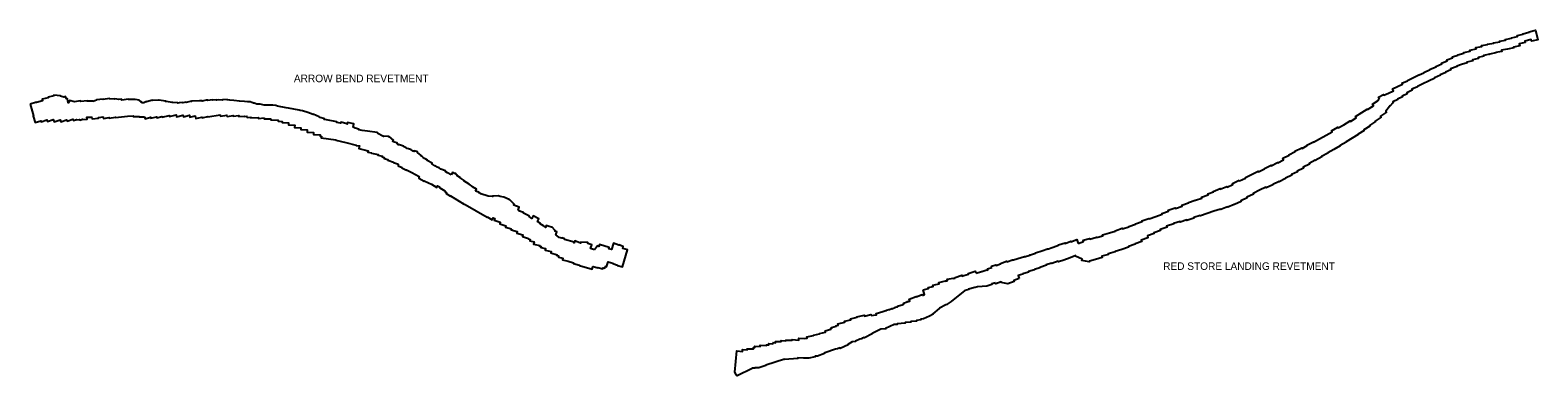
# Model space of a CAD drawing. Extents: x 2650582 to 3923188, y 277893 to 989177.
# Drawn here: x 3228750 to 3260686, y 811900 to 819222 of the extents above; entities that cross this region are included whole.
import ezdxf

# ---------------------------------------------------------------- set-up
doc = ezdxf.new("R2010")
doc.units = 0
doc.layers.add('Level 3', color=7, linetype='Continuous')

msp = doc.modelspace()

# ---------------------------------------------------------------- linework, layer by layer
at = {"layer": 'Level 3'}
for points in [[(3258408, 818391), (3258408, 818393), (3258531, 818448), (3258528, 818455), (3258651, 818509), (3258645, 818526), (3258768, 818574), (3258760, 818595), (3258880, 818639), (3258875, 818654), (3258990, 818691), (3258988, 818697), (3259120, 818737), (3259118, 818746), (3259253, 818779), (3259248, 818801), (3259377, 818827), (3259371, 818852), (3259498, 818879), (3259494, 818896), (3259621, 818920), (3259620, 818926), (3259750, 818949), (3259749, 818953), (3259877, 818976), (3259875, 818991), (3259999, 819013), (3259996, 819028), (3260127, 819056), (3260126, 819061), (3260252, 819087), (3260247, 819107), (3260374, 819135), (3260371, 819146), (3260504, 819178), (3260502, 819189), (3260634, 819222), (3260686, 819020), (3260552, 818987), (3260543, 819022), (3260407, 818990), (3260414, 818958)], [(3260414, 818958), (3260292, 818931), (3260301, 818887), (3260173, 818860), (3260175, 818850), (3260046, 818823), (3260046, 818820), (3259915, 818797), (3259920, 818772), (3259794, 818749), (3259795, 818740), (3259665, 818717), (3259666, 818712), (3259538, 818687), (3259542, 818670), (3259421, 818644), (3259426, 818621), (3259304, 818595), (3259309, 818575), (3259181, 818542), (3259185, 818529), (3259070, 818494), (3259071, 818493), (3258972, 818461), (3258975, 818453), (3258837, 818402), (3258846, 818380), (3258733, 818335), (3258736, 818327), (3258619, 818275), (3258621, 818269), (3258500, 818214), (3258503, 818207)], [(3257331, 817758), (3257307, 817805), (3257417, 817861), (3257423, 817847), (3257519, 817889), (3257519, 817891), (3257625, 817937), (3257605, 817982), (3257711, 818029), (3257710, 818031), (3257817, 818079), (3257808, 818099), (3257927, 818152), (3257924, 818159), (3258041, 818213), (3258040, 818216), (3258168, 818275), (3258169, 818273), (3258273, 818321), (3258270, 818328), (3258408, 818391)], [(3258503, 818207), (3258366, 818144), (3258368, 818139), (3258251, 818085), (3258252, 818082), (3258133, 818028), (3258135, 818024), (3258018, 817969), (3258026, 817951), (3257908, 817898), (3257920, 817871), (3257811, 817823), (3257817, 817809), (3257714, 817763), (3257718, 817753), (3257613, 817707), (3257623, 817684), (3257616, 817680), (3257555, 817623)], [(3230083, 817714), (3230084, 817719), (3229957, 817719), (3229956, 817727), (3229823, 817709), (3229820, 817728), (3229692, 817704), (3229582, 817735), (3229566, 817686), (3229557, 817684), (3229541, 817770), (3229521, 817765), (3229500, 817818), (3229466, 817802), (3229392, 817824), (3229393, 817834), (3229255, 817843), (3229254, 817831), (3229132, 817806), (3229135, 817789), (3229005, 817758), (3229010, 817726), (3228886, 817692), (3228884, 817697), (3228750, 817654)], [(3228750, 817654), (3228823, 817407)], [(3230839, 817754), (3230834, 817753), (3230832, 817762), (3230690, 817741), (3230688, 817760), (3230632, 817753), (3230631, 817757), (3230542, 817771), (3230540, 817763), (3230429, 817767), (3230428, 817773), (3230297, 817754), (3230296, 817762), (3230155, 817748), (3230156, 817742), (3230083, 817714)], [(3231110, 817683), (3231109, 817707), (3231100, 817707), (3231056, 817742), (3230974, 817751), (3230975, 817756), (3230839, 817754)], [(3233752, 817637), (3233704, 817637), (3233625, 817652), (3233555, 817655), (3233483, 817681), (3233481, 817677), (3233413, 817702), (3233360, 817701), (3233293, 817712), (3233187, 817715), (3233061, 817734), (3232978, 817740), (3232923, 817748), (3232923, 817752), (3232824, 817747), (3232823, 817738), (3232732, 817744), (3232697, 817739), (3232696, 817744), (3232613, 817741), (3232612, 817746), (3232516, 817733), (3232515, 817740), (3232481, 817739), (3232395, 817721), (3232394, 817726), (3232337, 817722), (3232336, 817728), (3232174, 817721), (3232167, 817714), (3232165, 817720), (3232052, 817690), (3232050, 817700), (3231981, 817683), (3231977, 817687), (3231907, 817684), (3231879, 817676), (3231876, 817681), (3231771, 817693), (3231760, 817689), (3231758, 817693), (3231631, 817713), (3231629, 817717), (3231618, 817714), (3231616, 817718), (3231480, 817739), (3231472, 817737), (3231471, 817739), (3231345, 817733), (3231342, 817739), (3231214, 817703), (3231212, 817708), (3231155, 817686), (3231110, 817683)], [(3236442, 816858), (3236445, 816867), (3236428, 816872), (3236444, 816889), (3236353, 816969), (3236343, 816961), (3236342, 816972), (3236238, 816980), (3236237, 816968), (3236221, 816975), (3236223, 816979), (3236118, 817037), (3236102, 817052), (3235894, 817086), (3235784, 817094), (3235709, 817113), (3235712, 817128), (3235632, 817147), (3235595, 817166), (3235609, 817236), (3235474, 817268), (3235465, 817232), (3235463, 817233), (3235465, 817240), (3235328, 817276), (3235323, 817254), (3235245, 817269), (3235246, 817279), (3235030, 817326), (3234976, 817328), (3234982, 817341), (3234895, 817369), (3234874, 817385), (3234744, 817440), (3234743, 817437), (3234633, 817478), (3234631, 817475), (3234519, 817516), (3234472, 817518), (3234448, 817530), (3234223, 817572), (3234174, 817575), (3233989, 817614), (3233954, 817624), (3233891, 817632), (3233752, 817637)], [(3257555, 817623), (3257546, 817611), (3257547, 817609), (3257543, 817607), (3257464, 817504), (3257477, 817483), (3257351, 817401), (3257365, 817379), (3257239, 817296), (3257245, 817286), (3257118, 817203), (3257129, 817186), (3256999, 817108), (3257007, 817095), (3256880, 817016), (3256882, 817013), (3256754, 816935), (3256755, 816932), (3256623, 816859), (3256628, 816850), (3256496, 816776), (3256499, 816771), (3256366, 816698), (3256367, 816695), (3256235, 816623), (3256238, 816618), (3256105, 816546), (3256109, 816539), (3255970, 816462), (3255967, 816467), (3255842, 816398), (3255848, 816387), (3255712, 816323), (3255723, 816300), (3255588, 816234), (3255593, 816223), (3255468, 816163), (3255473, 816152), (3255337, 816086), (3255340, 816081), (3255203, 816013), (3255203, 816015), (3255070, 815950), (3255070, 815949), (3254929, 815880), (3254921, 815895), (3254790, 815831), (3254791, 815830), (3254654, 815765), (3254660, 815751), (3254524, 815688), (3254532, 815670), (3254393, 815606), (3254398, 815594), (3254257, 815528), (3254256, 815531)], [(3254362, 816043), (3254368, 816030), (3254496, 816089), (3254491, 816100), (3254623, 816163), (3254621, 816168), (3254761, 816236), (3254768, 816222), (3254898, 816285), (3254895, 816293), (3255035, 816361), (3255040, 816352), (3255174, 816418), (3255175, 816414), (3255299, 816474), (3255281, 816511), (3255415, 816576), (3255411, 816584), (3255546, 816649), (3255540, 816662), (3255685, 816730), (3255691, 816719), (3255797, 816777), (3255793, 816783), (3255932, 816860), (3255937, 816852), (3256063, 816921), (3256062, 816923), (3256201, 816999), (3256327, 817068), (3256314, 817091), (3256451, 817168), (3256459, 817153), (3256576, 817216), (3256573, 817220), (3256707, 817301), (3256714, 817289), (3256839, 817366), (3256820, 817397), (3256954, 817478), (3256955, 817475), (3257073, 817551), (3257079, 817542), (3257201, 817622), (3257181, 817653), (3257306, 817734), (3257302, 817740), (3257331, 817758)], [(3228823, 817407), (3228814, 817404), (3228857, 817266), (3228973, 817304), (3228981, 817279), (3229104, 817322), (3229116, 817287), (3229237, 817329), (3229256, 817278), (3229384, 817322), (3229400, 817282), (3229522, 817323), (3229531, 817298), (3229653, 817339), (3229665, 817307), (3229732, 817329), (3229733, 817323), (3229794, 817333), (3229800, 817318), (3229856, 817337), (3229859, 817327), (3229956, 817339), (3229954, 817377), (3229965, 817381), (3230046, 817382), (3230047, 817381), (3230050, 817382), (3230057, 817382), (3230061, 817346), (3230198, 817361), (3230197, 817371), (3230300, 817384), (3230306, 817352), (3230423, 817373), (3230425, 817359), (3230556, 817377), (3230558, 817369), (3230812, 817401)], [(3230812, 817401), (3230934, 817410), (3230935, 817394), (3231059, 817394), (3231060, 817385), (3231171, 817384)], [(3231171, 817384), (3231184, 817341), (3231299, 817378), (3231304, 817356), (3231430, 817388), (3231436, 817367), (3231539, 817393), (3231543, 817378), (3231695, 817417), (3231701, 817395), (3231842, 817431), (3231852, 817389), (3231984, 817424), (3231996, 817389), (3232123, 817421), (3232135, 817381), (3232246, 817409), (3232259, 817354), (3232388, 817381), (3232392, 817366), (3232515, 817392), (3232517, 817386), (3232778, 817430), (3232784, 817404), (3232914, 817425), (3232920, 817395), (3233048, 817417), (3233051, 817398), (3233168, 817413), (3233171, 817394), (3233287, 817403), (3233288, 817395), (3233342, 817399), (3233344, 817374), (3233426, 817380), (3233427, 817363), (3233581, 817374), (3233584, 817350), (3233704, 817362)], [(3233704, 817362), (3233706, 817344), (3233844, 817344), (3233845, 817324), (3234004, 817313), (3234003, 817292), (3234087, 817288), (3234086, 817269), (3234222, 817262), (3234221, 817219), (3234355, 817213), (3234353, 817162), (3234487, 817156), (3234486, 817117), (3234620, 817112), (3234618, 817064), (3234750, 817056), (3234749, 817010), (3234894, 817002), (3234894, 816975), (3234923, 816974)], [(3234923, 816974), (3234917, 816943), (3235224, 816896), (3235223, 816893), (3235434, 816844), (3235657, 816788), (3235656, 816777), (3235723, 816769), (3235713, 816717), (3235882, 816675), (3235881, 816669), (3235908, 816663), (3235902, 816639), (3235980, 816621)], [(3235980, 816621), (3235980, 816617), (3236120, 816590), (3236117, 816575), (3236210, 816553), (3236206, 816540), (3236250, 816524), (3236246, 816505), (3236330, 816484), (3236324, 816469), (3236449, 816425), (3236448, 816419), (3236489, 816405), (3236488, 816403), (3236529, 816390), (3236543, 816385), (3236543, 816349), (3236631, 816314)], [(3237668, 816159), (3237588, 816202), (3237587, 816201), (3237558, 816224), (3237548, 816244), (3237450, 816281), (3237415, 816306), (3237369, 816323), (3237320, 816351), (3237261, 816388), (3237268, 816402), (3237162, 816459), (3237167, 816470), (3237130, 816487), (3237105, 816506), (3237075, 816522), (3237054, 816544), (3237027, 816563), (3237031, 816568), (3236955, 816634), (3236957, 816644), (3236886, 816664), (3236883, 816652), (3236862, 816661), (3236813, 816692), (3236735, 816714), (3236718, 816729), (3236658, 816756), (3236660, 816764), (3236613, 816776), (3236577, 816792), (3236545, 816792), (3236528, 816814), (3236522, 816817), (3236527, 816836), (3236468, 816851), (3236442, 816858)], [(3236631, 816314), (3236625, 816304), (3236719, 816254), (3236725, 816263), (3236791, 816230), (3236790, 816228), (3236832, 816210), (3236992, 816122), (3236986, 816101), (3236980, 816089), (3237096, 816027), (3237097, 816029), (3237188, 815992), (3237186, 815987), (3237253, 815960), (3237364, 815892), (3237378, 815922), (3237419, 815904), (3237423, 815901), (3237419, 815889), (3237431, 815884), (3237430, 815884), (3237534, 815818), (3237532, 815812), (3237548, 815806), (3237544, 815796), (3237571, 815785), (3237560, 815764), (3237653, 815707), (3237656, 815712), (3237929, 815546), (3237930, 815548), (3237935, 815545), (3237934, 815540), (3237961, 815530), (3238429, 815264), (3238431, 815269)], [(3237702, 816212), (3237668, 816159)], [(3238183, 815813), (3238208, 815851), (3238123, 815901), (3238126, 815907), (3238047, 815957), (3238049, 815960), (3237939, 816030), (3237945, 816040), (3237862, 816092), (3237865, 816097), (3237789, 816147), (3237792, 816152), (3237780, 816160), (3237756, 816196), (3237740, 816186), (3237702, 816212)], [(3250948, 814707), (3251062, 814744), (3251054, 814771), (3251191, 814810), (3251195, 814795), (3251334, 814836), (3251336, 814829), (3251471, 814868), (3251466, 814886), (3251611, 814928), (3251611, 814930), (3251735, 814966), (3251733, 814973), (3251880, 815025), (3251885, 815011), (3252022, 815058), (3252021, 815063), (3252165, 815111), (3252162, 815119), (3252304, 815167), (3252299, 815182), (3252449, 815233), (3252451, 815229), (3252592, 815278), (3252593, 815275), (3252730, 815322), (3252724, 815341), (3252865, 815389), (3252858, 815411), (3253006, 815461), (3253011, 815448), (3253150, 815495), (3253142, 815518), (3253285, 815566), (3253283, 815573), (3253430, 815623), (3253431, 815619), (3253566, 815666), (3253559, 815686), (3253704, 815735), (3253697, 815757), (3253815, 815796), (3253811, 815806), (3253954, 815866), (3253960, 815854), (3254098, 815913), (3254105, 815898), (3254226, 815954), (3254215, 815977), (3254362, 816043)], [(3239088, 815413), (3239109, 815471), (3238994, 815517), (3238997, 815527), (3239004, 815535), (3238902, 815633), (3238899, 815631), (3238893, 815634), (3238894, 815637), (3238783, 815688), (3238781, 815685), (3238703, 815700), (3238667, 815713), (3238666, 815710), (3238553, 815705), (3238553, 815702), (3238538, 815706), (3238537, 815701), (3238454, 815709), (3238454, 815704), (3238294, 815759), (3238292, 815753), (3238287, 815758), (3238289, 815765), (3238253, 815778), (3238256, 815789), (3238183, 815813)], [(3240706, 814569), (3240643, 814590), (3240644, 814593), (3240620, 814600), (3240648, 814677), (3240561, 814706), (3240560, 814726), (3240418, 814730), (3240411, 814708), (3240285, 814757), (3240270, 814720), (3240269, 814720), (3240271, 814731), (3240067, 814789), (3240071, 814799), (3240016, 814823), (3240014, 814820), (3239958, 814834), (3239913, 814866), (3239913, 814865), (3239892, 814879), (3239893, 814884), (3239883, 814888), (3239906, 814951), (3239861, 814966), (3239871, 814977), (3239799, 815056), (3239795, 815053), (3239743, 815063), (3239742, 815062), (3239679, 815082), (3239665, 815043), (3239657, 815049), (3239658, 815059), (3239639, 815064), (3239641, 815067), (3239634, 815071), (3239634, 815073), (3239622, 815079), (3239554, 815121), (3239556, 815130), (3239552, 815131), (3239553, 815134), (3239532, 815142), (3239535, 815147), (3239498, 815170), (3239527, 815225), (3239406, 815288), (3239377, 815234), (3239320, 815275), (3239322, 815287), (3239310, 815290), (3239199, 815348), (3239201, 815360), (3239138, 815381), (3239125, 815389), (3239088, 815413)], [(3254256, 815531), (3254116, 815472), (3254112, 815481), (3253972, 815422), (3253967, 815434), (3253819, 815386), (3253819, 815386), (3253680, 815340), (3253679, 815342), (3253538, 815293), (3253536, 815298), (3253399, 815251), (3253402, 815243), (3253252, 815192), (3253248, 815205), (3253111, 815158), (3253107, 815171), (3252971, 815124), (3252973, 815120), (3252823, 815069), (3252831, 815048), (3252688, 814999), (3252694, 814981), (3252552, 814931), (3252557, 814915), (3252414, 814866), (3252428, 814826), (3252286, 814777), (3252297, 814743), (3252154, 814695), (3252157, 814686), (3252015, 814637), (3252018, 814627), (3251874, 814576), (3251875, 814573), (3251730, 814531), (3251732, 814527), (3251587, 814486), (3251590, 814474), (3251449, 814433), (3251457, 814407), (3251317, 814367), (3251316, 814368), (3251187, 814331), (3251182, 814312), (3251029, 814347), (3251034, 814371), (3250894, 814432), (3250901, 814447)], [(3238431, 815269), (3238535, 815205), (3238559, 815245), (3238591, 815235), (3238580, 815197), (3238707, 815155), (3238697, 815119), (3238827, 815079), (3238819, 815052), (3238943, 815014)], [(3238943, 815014), (3238939, 814995), (3239068, 814958), (3239059, 814924), (3239187, 814887), (3239179, 814854), (3239308, 814813), (3239305, 814800), (3239342, 814787), (3239336, 814762), (3239425, 814737), (3239413, 814692), (3239544, 814659), (3239541, 814649), (3239573, 814641), (3239568, 814618), (3239666, 814595), (3239658, 814564), (3239789, 814531), (3239782, 814503), (3239912, 814467), (3239908, 814452), (3239945, 814441), (3239940, 814417), (3240030, 814393), (3240024, 814359), (3240149, 814328), (3240261, 814293), (3240258, 814282), (3240389, 814244), (3240388, 814239), (3240652, 814158), (3240669, 814212)], [(3240669, 814212), (3240675, 814211), (3240677, 814217), (3240776, 814188), (3240778, 814195), (3240879, 814164), (3240887, 814191), (3240921, 814182), (3240932, 814219), (3240959, 814212), (3240992, 814317), (3241091, 814287), (3241089, 814278), (3241191, 814244), (3241189, 814239), (3241294, 814209), (3241405, 814567), (3241301, 814601), (3241314, 814639), (3241218, 814674), (3241217, 814671), (3241106, 814709), (3241062, 814578), (3241011, 814594), (3241018, 814618), (3240810, 814683), (3240795, 814640), (3240771, 814655), (3240706, 814569)], [(3249557, 814352), (3249672, 814384), (3249671, 814388), (3249809, 814427), (3249811, 814421), (3249922, 814454), (3249921, 814457), (3250046, 814496), (3250044, 814506), (3250177, 814549), (3250177, 814547), (3250296, 814589), (3250299, 814582), (3250418, 814625), (3250416, 814629), (3250531, 814670), (3250530, 814673), (3250670, 814721), (3250675, 814705), (3250792, 814751), (3250797, 814739), (3250918, 814786), (3250948, 814707)], [(3249121, 814192), (3249115, 814221), (3249205, 814251), (3249209, 814240), (3249307, 814276), (3249304, 814282), (3249434, 814329), (3249440, 814313), (3249556, 814356), (3249557, 814352)], [(3250901, 814447), (3250900, 814447), (3250781, 814401), (3250781, 814400), (3250642, 814351), (3250642, 814352), (3250529, 814312), (3250524, 814326), (3250390, 814278), (3250386, 814290), (3250274, 814250), (3250276, 814243), (3250134, 814197), (3250135, 814191), (3250023, 814156), (3250026, 814146), (3249897, 814109), (3249900, 814097), (3249774, 814063), (3249776, 814057), (3249675, 814029), (3249700, 813961)], [(3248345, 813969), (3248341, 813982), (3248487, 814032), (3248493, 814014), (3248530, 814023), (3248624, 814056), (3248619, 814070), (3248768, 814121), (3248785, 814073)], [(3248785, 814073), (3248903, 814114), (3248905, 814110), (3249015, 814144), (3249016, 814141), (3249036, 814148), (3249031, 814164), (3249121, 814192)], [(3247653, 813605), (3247691, 813620), (3247666, 813724)], [(3247666, 813724), (3247777, 813751), (3247773, 813770), (3247878, 813795), (3247872, 813819), (3247934, 813835), (3247934, 813837), (3247967, 813843), (3248005, 813852), (3247999, 813876), (3248139, 813912), (3248139, 813909), (3248182, 813919), (3248176, 813947), (3248303, 813970), (3248305, 813959), (3248345, 813969)], [(3249196, 813873), (3249119, 813850), (3249123, 813834), (3249017, 813799), (3249016, 813802), (3248815, 813783), (3248815, 813785), (3248764, 813770), (3248763, 813771), (3248628, 813737), (3248630, 813730), (3248580, 813716), (3248550, 813707), (3248259, 813476)], [(3249700, 813961), (3249583, 813919), (3249591, 813896), (3249461, 813849), (3249461, 813850), (3249460, 813846), (3249316, 813876), (3249319, 813893), (3249205, 813850), (3249196, 813873)], [(3248259, 813476), (3248262, 813472), (3248175, 813419), (3248177, 813415), (3248147, 813401), (3248015, 813337), (3248011, 813334), (3248012, 813329), (3248004, 813328), (3247873, 813212), (3247876, 813207), (3247801, 813165), (3247802, 813162), (3247671, 813109), (3247613, 813100), (3247615, 813087), (3247526, 813072), (3247527, 813062), (3247405, 813050), (3247406, 813038), (3247285, 813027), (3247286, 813015), (3247117, 812999), (3247118, 812991), (3247053, 812985), (3246871, 812904), (3246872, 812897), (3246766, 812887), (3246582, 812797), (3246585, 812791), (3246425, 812704), (3246418, 812716), (3246366, 812691), (3246367, 812685), (3246327, 812680), (3246229, 812635), (3246230, 812628), (3246163, 812618), (3246073, 812564), (3246075, 812559), (3245907, 812479), (3245899, 812495), (3245849, 812473), (3245807, 812468)], [(3246562, 813181), (3246662, 813192), (3246675, 813196), (3246669, 813219), (3246812, 813262), (3246812, 813260), (3246856, 813275), (3246856, 813280), (3246877, 813281), (3246891, 813286), (3246890, 813289), (3246942, 813306), (3246942, 813308), (3246951, 813309), (3247000, 813325), (3247001, 813322), (3247072, 813346), (3247071, 813356), (3247113, 813360), (3247123, 813363), (3247120, 813373), (3247242, 813414), (3247241, 813421), (3247257, 813423), (3247252, 813439), (3247330, 813466), (3247329, 813472), (3247357, 813475), (3247382, 813483), (3247367, 813527), (3247514, 813578), (3247516, 813574), (3247648, 813620), (3247653, 813605)], [(3245587, 812856), (3245713, 812886), (3245708, 812909), (3245728, 812913), (3245724, 812927), (3245821, 812950), (3245818, 812961), (3245866, 812972), (3245859, 813002), (3246004, 813036), (3246000, 813055), (3246131, 813086), (3246125, 813109), (3246265, 813141), (3246263, 813147), (3246417, 813183), (3246421, 813163), (3246557, 813199), (3246562, 813181)], [(3245159, 812689), (3245211, 812701), (3245205, 812727), (3245345, 812757), (3245344, 812760), (3245471, 812792), (3245470, 812797), (3245594, 812827), (3245587, 812856)], [(3245807, 812468), (3245586, 812386), (3245586, 812384), (3245571, 812381), (3245570, 812380), (3245573, 812371), (3245424, 812317), (3245378, 812315), (3245380, 812303), (3245243, 812275), (3245132, 812278), (3245132, 812272), (3245008, 812280), (3245009, 812268), (3244731, 812244), (3244731, 812252), (3244333, 812126), (3244336, 812117), (3244184, 812069), (3244099, 812073), (3244099, 812063), (3244041, 812064), (3244044, 812059), (3243724, 811900), (3243716, 811915), (3243711, 811913), (3243680, 811980), (3243717, 812427), (3243838, 812417), (3243841, 812458), (3243941, 812450), (3243941, 812473), (3244074, 812469), (3244074, 812504), (3244098, 812504), (3244099, 812527), (3244210, 812521), (3244212, 812553), (3244347, 812545), (3244347, 812560), (3244398, 812559), (3244399, 812583), (3244484, 812579), (3244485, 812605), (3244537, 812603), (3244539, 812630), (3244621, 812625), (3244621, 812631), (3244659, 812627), (3244660, 812648), (3244754, 812645), (3244755, 812659), (3244888, 812653), (3244889, 812667), (3245031, 812658), (3245034, 812700), (3245159, 812692), (3245159, 812689)]]:
    msp.add_lwpolyline(points, dxfattribs=at)

# ---------------------------------------------------------------- texts
for s, p in [('ARROW BEND REVETMENT', (3234337, 818120)), ('RED STORE LANDING REVETMENT', (3252749, 814144))]:
    msp.add_text(s, height=160, dxfattribs=at).set_placement(p)

doc.saveas('drawing.dxf')
